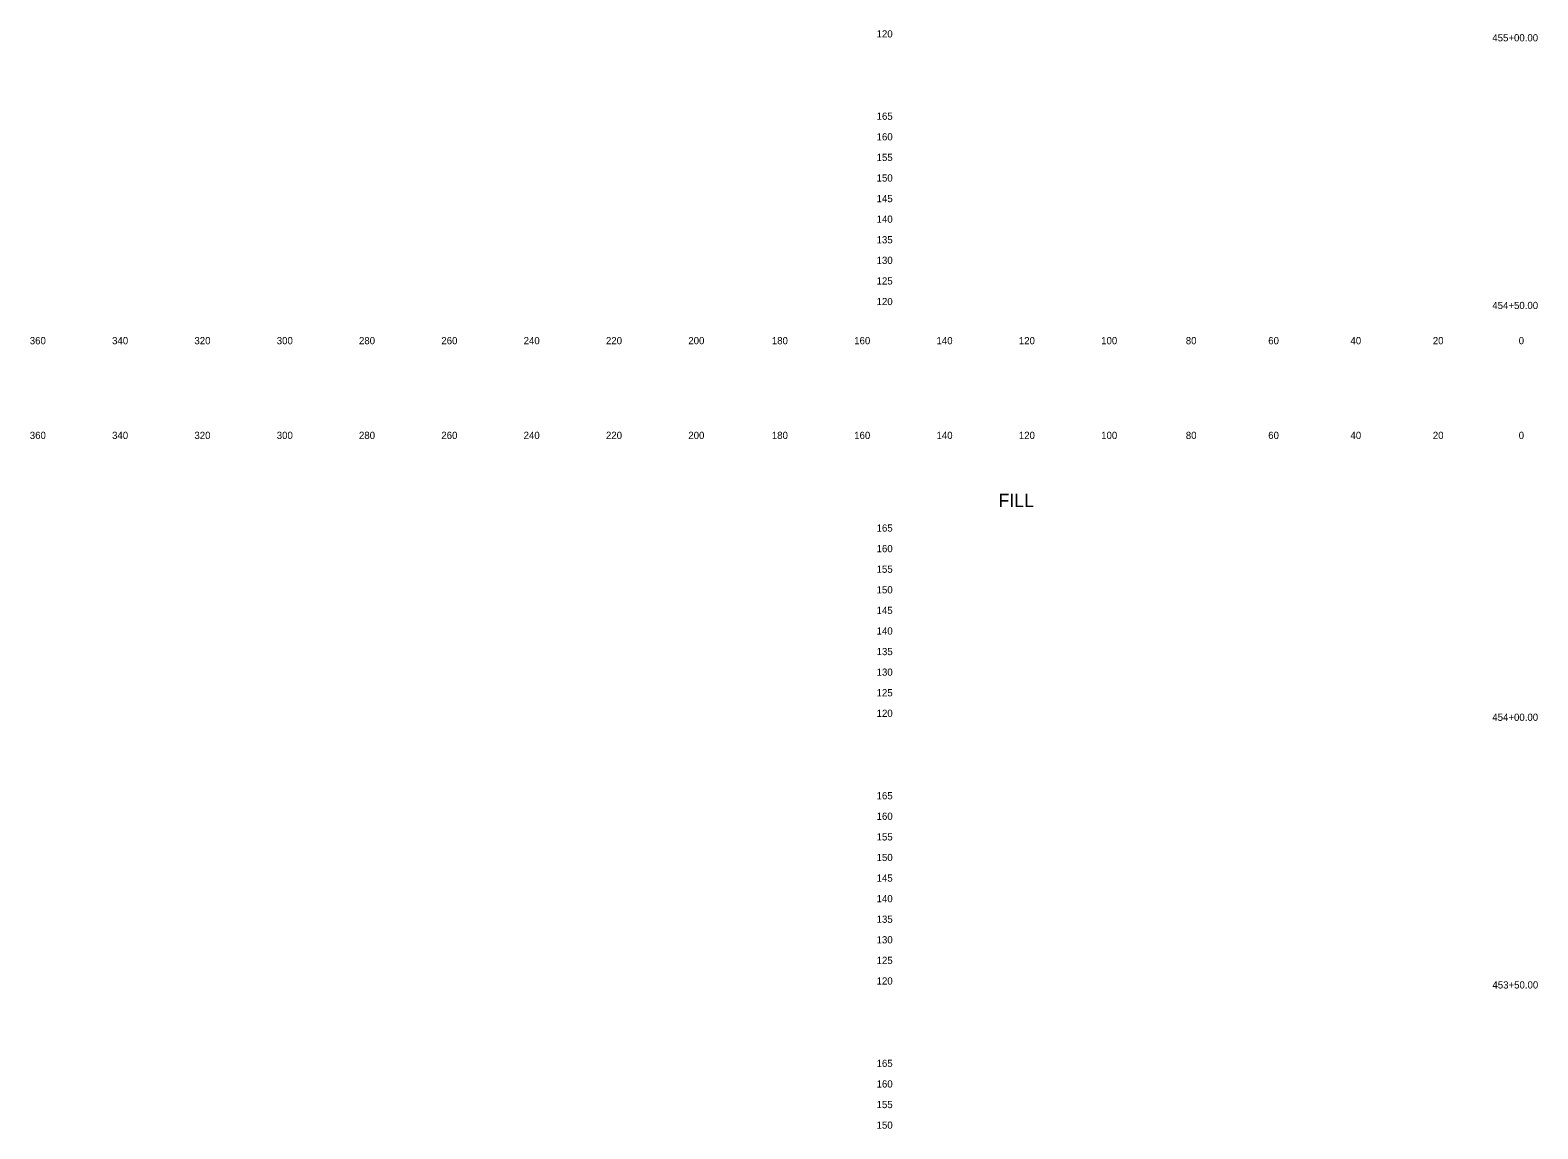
# Model space of a CAD drawing. Extents: x 21281 to 22024, y 6472 to 15198.
# Drawn here: x 21280.5 to 21646.8, y 6744.8 to 7011.6 of the extents above; entities that cross this region are included whole.
import ezdxf

# ---------------------------------------------------------------- set-up
doc = ezdxf.new("R2010")
doc.units = 0
for name, color, linetype in [('XS_SHEET_LABELS_ELEVATION', 7, 'Continuous'), ('XS_SHEET_LABELS_OFFSET', 7, 'Continuous'), ('XS_SHEET_LABELS_STATION', 7, 'Continuous')]:
    doc.layers.add(name, color=color, linetype=linetype)

msp = doc.modelspace()

# ---------------------------------------------------------------- texts
at = {"layer": 'XS_SHEET_LABELS_ELEVATION'}
for s, p in [('  120  ', (21484.84, 7009.84)), ('  165  ', (21484.84, 6989.84)), ('  160  ', (21484.84, 6984.84)), ('  155  ', (21484.84, 6979.84)), ('  150  ', (21484.84, 6974.84)), ('  145  ', (21484.84, 6969.84)), ('  140  ', (21484.84, 6964.84)), ('  135  ', (21484.84, 6959.84)), ('  130  ', (21484.84, 6954.84)), ('  125  ', (21484.84, 6949.84)), ('  120  ', (21484.84, 6944.84)), ('  165  ', (21484.84, 6889.84)), ('  160  ', (21484.84, 6884.84)), ('  155  ', (21484.84, 6879.84)), ('  150  ', (21484.84, 6874.84)), ('  145  ', (21484.84, 6869.84)), ('  140  ', (21484.84, 6864.84)), ('  135  ', (21484.84, 6859.84)), ('  130  ', (21484.84, 6854.84)), ('  125  ', (21484.84, 6849.84)), ('  120  ', (21484.84, 6844.84)), ('  165  ', (21484.84, 6824.84)), ('  160  ', (21484.84, 6819.84)), ('  155  ', (21484.84, 6814.84)), ('  150  ', (21484.84, 6809.84)), ('  145  ', (21484.84, 6804.84)), ('  140  ', (21484.84, 6799.84)), ('  135  ', (21484.84, 6794.84)), ('  130  ', (21484.84, 6789.84)), ('  125  ', (21484.84, 6784.84)), ('  120  ', (21484.84, 6779.84)), ('  165  ', (21484.84, 6759.84)), ('  160  ', (21484.84, 6754.84)), ('  155  ', (21484.84, 6749.84)), ('  150  ', (21484.84, 6744.84))]:
    msp.add_text(s, height=1.75, dxfattribs=at).set_placement(p)
at = {"layer": 'XS_SHEET_LABELS_OFFSET'}
for s, height, p in [('  360  ', 1.75, (21279.14, 6935.34)), ('  340  ', 1.75, (21299.13, 6935.34)), ('  320  ', 1.75, (21319.13, 6935.34)), ('  300  ', 1.75, (21339.13, 6935.34)), ('  280  ', 1.75, (21359.1, 6935.34)), ('  260  ', 1.75, (21379.11, 6935.34)), ('  240  ', 1.75, (21399.1, 6935.34)), ('  220  ', 1.75, (21419.1, 6935.34)), ('  200  ', 1.75, (21439.1, 6935.34)), ('  180  ', 1.75, (21459.39, 6935.34)), ('  160  ', 1.75, (21479.4, 6935.34)), ('  140  ', 1.75, (21499.39, 6935.34)), ('  120  ', 1.75, (21519.39, 6935.34)), ('  100  ', 1.75, (21539.39, 6935.34)), ('  80  ', 1.75, (21559.95, 6935.34)), ('  60  ', 1.75, (21579.97, 6935.34)), ('  40  ', 1.75, (21599.95, 6935.34)), ('  20  ', 1.75, (21619.95, 6935.34)), ('  0  ', 1.75, (21640.81, 6935.34)), ('  0  ', 1.75, (21640.81, 6935.34)), ('  360  ', 1.75, (21279.14, 6912.34)), ('  340  ', 1.75, (21299.13, 6912.34)), ('  320  ', 1.75, (21319.13, 6912.34)), ('  300  ', 1.75, (21339.13, 6912.34)), ('  280  ', 1.75, (21359.1, 6912.34)), ('  260  ', 1.75, (21379.11, 6912.34)), ('  240  ', 1.75, (21399.1, 6912.34)), ('  220  ', 1.75, (21419.1, 6912.34)), ('  200  ', 1.75, (21439.1, 6912.34)), ('  180  ', 1.75, (21459.39, 6912.34)), ('  160  ', 1.75, (21479.4, 6912.34)), ('  140  ', 1.75, (21499.39, 6912.34)), ('  120  ', 1.75, (21519.39, 6912.34)), ('  100  ', 1.75, (21539.39, 6912.34)), ('  80  ', 1.75, (21559.95, 6912.34)), ('  60  ', 1.75, (21579.97, 6912.34)), ('  40  ', 1.75, (21599.95, 6912.34)), ('  20  ', 1.75, (21619.95, 6912.34)), ('  0  ', 1.75, (21640.81, 6912.34)), ('  0  ', 1.75, (21640.81, 6912.34)), ('FILL', 3.222, (21515.74, 6895.82))]:
    msp.add_text(s, height=height, dxfattribs=at).set_placement(p)
at = {"layer": 'XS_SHEET_LABELS_STATION'}
for s, p in [('  455+00.00  ', (21634.4, 7008.89)), ('  454+50.00  ', (21634.4, 6943.89)), ('  454+00.00  ', (21634.4, 6843.89)), ('  453+50.00  ', (21634.43, 6778.89))]:
    msp.add_text(s, height=1.75, dxfattribs=at).set_placement(p)

doc.saveas('drawing.dxf')
